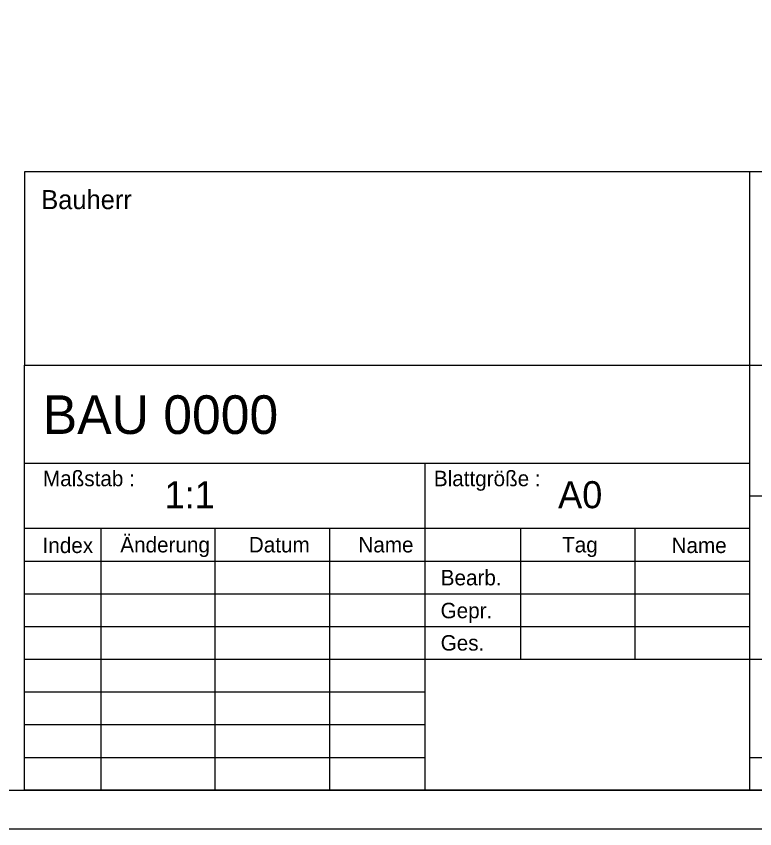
# Model space of a CAD drawing. Extents: x 0 to 1189, y 0 to 841.
# Drawn here: x 1005.1 to 1100.7, y 0 to 105.1 of the extents above; entities that cross this region are included whole.
import ezdxf

# ---------------------------------------------------------------- set-up
doc = ezdxf.new("R2010")
doc.units = 0
doc.layers.add('90_Plankopf', color=7, linetype='Continuous')

msp = doc.modelspace()

# ---------------------------------------------------------------- linework, layer by layer
at = {"layer": '90_Plankopf'}
for p, q in [((1184, 84.99), (1006.12, 84.99)), ((1006.12, 84.99), (1006.12, 59.99)), ((1100, 59.99), (1100, 84.99)), ((1006.12, 59.99), (1184, 59.99)), ((1006.12, 5), (1006.12, 59.99)), ((1006.12, 59.99), (1184, 59.99)), ((1100, 5), (1100, 59.99)), ((1006.12, 47.3), (1100, 47.3)), ((1058, 5), (1058, 47.3)), ((1100, 43.07), (1184, 43.07)), ((1006.12, 38.87), (1100, 38.87)), ((1016, 38.84), (1016, 5)), ((1030.83, 5), (1030.83, 38.84)), ((1045.65, 5), (1045.65, 38.84)), ((1070.35, 38.84), (1070.35, 21.92)), ((1085.18, 21.92), (1085.18, 38.84)), ((1006.12, 34.63), (1100, 34.63)), ((1006.12, 30.38), (1100, 30.38)), ((1006.12, 26.15), (1100, 26.15)), ((1006.12, 21.92), (1100, 21.92)), ((1006.12, 21.92), (1100, 21.92)), ((1058, 21.92), (1100, 21.92)), ((1100, 21.92), (1184, 21.92)), ((1058, 17.69), (1006.12, 17.69)), ((1058, 13.46), (1006.12, 13.46)), ((1006.12, 9.23), (1058, 9.23)), ((1100, 9.23), (1184, 9.23)), ((1184, 5), (1006.12, 5)), ((1006.12, 5), (1058, 5)), ((1017.8, 5), (1184, 5)), ((1017.8, 5), (1184, 5))]:
    msp.add_line(p, q, dxfattribs=at)
for points in [[(0, 0), (1189, 0), (1189, 841), (0, 841)], [(25, 5), (1184, 5), (1184, 836), (25, 836)]]:
    msp.add_lwpolyline(points, close=True, dxfattribs=at)

# ---------------------------------------------------------------- texts
for s, height, p in [('Bauherr', 2.464, (1008.3, 80.17)), ('BAU 0000      ', 5, (1008.49, 51.08)), ('Maßstab :', 2, (1008.52, 44.32)), ('Blattgröße :', 1.9999, (1059.12, 44.32)), ('1:1      ', 3.5, (1024.26, 41.47)), ('A0       ', 3.5, (1075.2, 41.47)), ('Änderung', 2, (1018.53, 35.75)), ('Index', 2, (1008.47, 35.67)), ('Datum', 2, (1035.17, 35.75)), ('Name', 2, (1049.35, 35.75)), ('Tag', 2, (1075.72, 35.75)), ('Name', 2, (1089.89, 35.67)), ('Bearb.', 2, (1060.01, 31.49)), ('Gepr.', 2, (1059.99, 27.23)), ('Ges.', 2, (1060, 23.05))]:
    msp.add_text(s, height=height, dxfattribs=at).set_placement(p)

doc.saveas('drawing.dxf')
